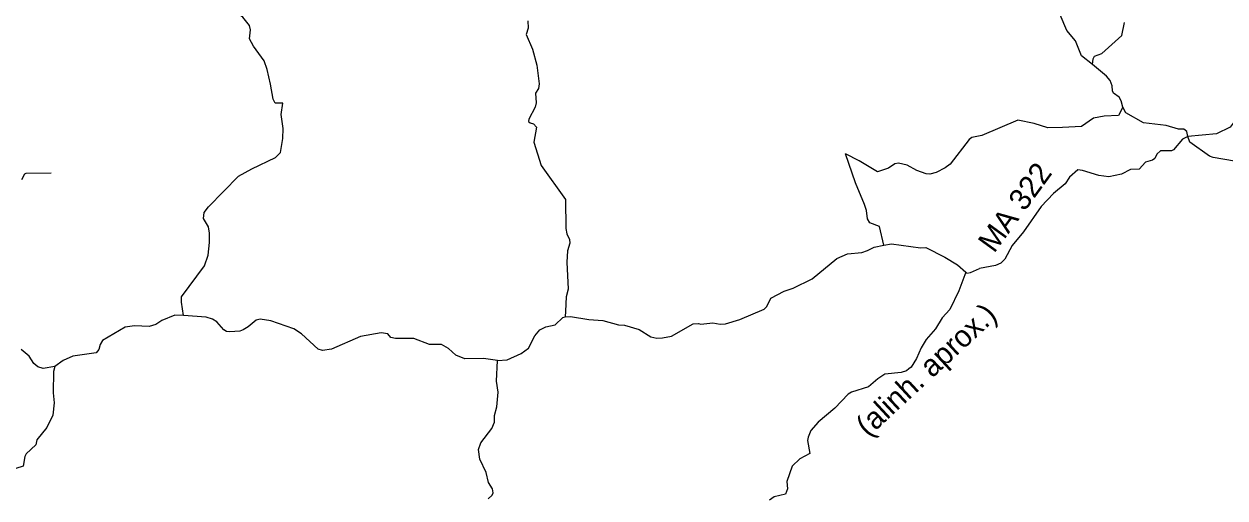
# Model space of a CAD drawing. Extents: x 332 to 501, y 9447 to 9559.
# Drawn here: x 427.75 to 448.76, y 9533.34 to 9541.64 of the extents above; entities that cross this region are included whole.
import ezdxf

# ---------------------------------------------------------------- set-up
doc = ezdxf.new("R2010")
doc.units = 0
for name, color, linetype in [('Level 31', 7, 'Continuous'), ('Level 5', 7, 'Continuous'), ('Level 6', 7, 'Continuous'), ('Level 7', 7, 'Continuous')]:
    doc.layers.add(name, color=color, linetype=linetype)

msp = doc.modelspace()

# ---------------------------------------------------------------- linework, layer by layer
at = {"layer": 'Level 5'}
for points in [[(432.2736, 9540.2543), (432.1396, 9540.2564), (432.1044, 9540.3252), (432.0629, 9540.5874), (432.0037, 9540.8432), (431.9493, 9540.9983), (431.7606, 9541.2542), (431.6919, 9541.3805), (431.7079, 9541.5404), (431.6935, 9541.6123), (431.5768, 9541.7626), (431.4281, 9541.857), (431.3849, 9541.9241), (431.3769, 9542.0329), (431.447, 9542.1738), (431.4412, 9542.3762), (431.5784, 9542.7652), (431.5944, 9542.8675), (431.4952, 9543.1745), (431.468, 9543.5839), (431.4041, 9543.7374), (431.2237, 9544.0586), (431.156, 9544.2217)], [(446.4423, 9540.9311), (446.2536, 9541.082), (446.1463, 9541.3459), (445.9948, 9541.5276), (445.88, 9541.8002)], [(446.4423, 9540.9311), (446.4579, 9541.0297), (446.4814, 9541.075), (446.6045, 9541.1224), (446.9578, 9541.4405), (447.0045, 9541.6664)], [(446.9746, 9540.1859), (446.9478, 9540.297), (446.9102, 9540.3612), (446.8127, 9540.432), (446.7939, 9540.4695), (446.7892, 9540.5571), (446.7509, 9540.6517), (446.6903, 9540.7249), (446.4423, 9540.9311)], [(430.5402, 9536.5403), (430.5036, 9536.7733), (430.5055, 9536.8634), (430.9036, 9537.4086), (430.9713, 9537.5924), (430.9947, 9537.818), (430.9915, 9537.9811), (430.9772, 9538.0898), (430.886, 9538.2353), (430.9022, 9538.3429), (430.974, 9538.4416), (431.5032, 9538.9772), (431.7367, 9539.1083), (432.1474, 9539.3034), (432.2352, 9539.392), (432.2771, 9539.6344), (432.2832, 9539.8105), (432.2472, 9540.0564), (432.2736, 9540.2543)], [(446.9746, 9540.1859), (446.8976, 9540.0372), (446.6488, 9540.0286), (446.46, 9539.9943), (446.254, 9539.8484), (445.9194, 9539.8313), (445.662, 9539.8227), (445.4217, 9539.8999), (445.1385, 9539.96), (444.5075, 9539.6862)], [(448.0425, 9539.8014), (447.9458, 9539.7996), (447.7353, 9539.8616), (447.3388, 9539.9106), (447.0244, 9540.0843), (446.9746, 9540.1859)], [(449.4204, 9540.23), (449.1918, 9540.2541), (449.0278, 9540.2528), (448.9486, 9540.1812), (448.922, 9539.9309), (448.8547, 9539.837), (448.6138, 9539.7165), (448.1107, 9539.6687)], [(448.1107, 9539.6687), (448.0163, 9539.6243), (447.863, 9539.4397), (447.8255, 9539.4178), (447.6315, 9539.4194), (447.5705, 9539.3615), (447.5372, 9539.2886), (447.4955, 9539.257), (447.3719, 9539.2216), (447.262, 9539.1018), (447.1068, 9539.0967), (446.9541, 9539.0147), (446.7282, 9538.9655), (446.5565, 9538.9894), (446.2713, 9539.0778), (446.1892, 9539.0879), (446.0395, 9538.9613)], [(448.1107, 9539.6687), (448.0925, 9539.7592), (448.0425, 9539.8014)], [(448.5551, 9539.3031), (448.493, 9539.3273), (448.1489, 9539.5746), (448.1107, 9539.6687)], [(448.9279, 9539.2381), (448.5551, 9539.3031)], [(446.0395, 9538.9613), (445.9646, 9538.843), (445.7588, 9538.6751), (445.548, 9538.4442), (445.2338, 9538.0037), (445.0381, 9537.7652), (444.9081, 9537.5216), (444.84, 9537.4559), (444.7491, 9537.4118), (444.4645, 9537.3604)], [(437.6307, 9536.4709), (437.8735, 9536.4493), (438.1517, 9536.3741), (438.2541, 9536.3693), (438.5099, 9536.2958), (438.7178, 9536.1662), (438.8201, 9536.1439), (438.9224, 9536.147), (439.0759, 9536.179), (439.4581, 9536.3933), (439.5524, 9536.3981), (439.5908, 9536.3853), (439.7987, 9536.4077), (439.9314, 9536.3869), (440.0202, 9536.3923), (440.275, 9536.4709), (440.7007, 9536.6519), (440.7449, 9536.6931), (440.814, 9536.8394), (441.0507, 9536.9657), (441.2058, 9537.0153), (441.5361, 9537.1774), (441.9701, 9537.5372), (442.1571, 9537.6164), (442.4064, 9537.644), (442.5047, 9537.674), (442.6222, 9537.7363), (442.7954, 9537.7712)], [(442.7954, 9537.7712), (442.9267, 9537.7903), (443.4315, 9537.7252), (443.5259, 9537.7284), (443.8604, 9537.5593), (444.0834, 9537.4238), (444.2303, 9537.296)], [(444.3068, 9537.2933), (444.4645, 9537.3604)], [(444.2303, 9537.296), (444.1049, 9536.9673), (443.9448, 9536.6459), (443.8121, 9536.4956), (443.6954, 9536.3022), (443.5307, 9536.1183), (443.4443, 9535.9744), (443.366, 9535.7873), (443.2731, 9535.635), (443.2291, 9535.602)], [(444.2303, 9537.296), (444.2456, 9537.2813), (444.3068, 9537.2933)], [(430.5402, 9536.5403), (430.388, 9536.5459), (430.1615, 9536.4516), (430.056, 9536.3803), (429.9394, 9536.3437), (429.6804, 9536.3597), (429.5173, 9536.3325), (429.1224, 9536.1007), (429.082, 9536.033), (429.0579, 9535.945), (429.0088, 9535.8848), (428.6027, 9535.8257), (428.4299, 9535.7489), (428.2847, 9535.646)], [(433.9992, 9536.234), (433.6363, 9536.1694), (433.1288, 9535.9511), (432.9679, 9535.928), (432.8944, 9535.9465), (432.6033, 9536.2174), (432.469, 9536.3069), (432.0693, 9536.4429), (431.8779, 9536.4724), (431.8118, 9536.4572), (431.6727, 9536.3373), (431.58, 9536.2846), (431.5224, 9536.2622), (431.3497, 9536.251), (431.2922, 9536.259), (431.2442, 9536.2862), (431.1211, 9536.4269), (431.0459, 9536.4716), (430.9372, 9536.5068), (430.5402, 9536.5403)], [(436.0331, 9535.7503), (436.2031, 9535.762), (436.4456, 9535.872), (436.5736, 9535.9648), (436.6839, 9536.1822), (436.7718, 9536.2862), (436.879, 9536.3389), (437.0421, 9536.3773), (437.1763, 9536.502), (437.2184, 9536.5173)], [(437.2184, 9536.5173), (437.3075, 9536.5212), (437.6307, 9536.4709)], [(436.0331, 9535.7503), (435.7885, 9535.7857), (435.4623, 9535.7793), (435.304, 9535.8448), (435.1761, 9535.9616), (435.0539, 9536.0299), (434.8419, 9536.0319), (434.5669, 9536.1343), (434.2496, 9536.1374), (434.1671, 9536.1534), (434.113, 9536.2169), (433.9992, 9536.234)], [(435.8684, 9533.3265), (435.9372, 9533.392), (435.9543, 9533.4367), (435.9475, 9533.5026), (435.8763, 9533.6142), (435.8316, 9533.7918), (435.7229, 9534.022), (435.7005, 9534.1947), (435.7421, 9534.3098), (435.934, 9534.5577), (435.9796, 9534.6702), (435.9819, 9534.7895), (436.0229, 9534.9388), (436.0459, 9535.1957), (436.0155, 9535.3916), (436.0331, 9535.7503)], [(428.2847, 9535.646), (428.262, 9535.557), (428.2553, 9535.1826), (428.2748, 9535.0102), (428.254, 9534.7927), (428.1485, 9534.5753), (427.9726, 9534.361), (427.9534, 9534.2731), (427.7871, 9534.1196), (427.7615, 9534.0716), (427.7343, 9533.9005), (427.4929, 9533.8237), (427.349, 9533.8062), (427.2531, 9533.8078), (427.0212, 9533.8669), (426.8693, 9533.8813), (426.7062, 9533.8221), (426.6519, 9533.8221), (426.6167, 9533.8317), (426.4008, 9533.9756), (426.2937, 9533.9756), (426.1306, 9533.9405)], [(443.2291, 9535.602), (443.1868, 9535.5703), (443.0981, 9535.5415), (442.8111, 9535.5107), (442.6858, 9535.4311), (442.5265, 9535.29), (442.2259, 9535.1973), (442.1684, 9535.1589), (441.9349, 9534.9142), (441.6423, 9534.6728), (441.5128, 9534.5241), (441.4664, 9534.409), (441.4584, 9534.3514), (441.4972, 9534.1199), (441.324, 9534.03), (441.1866, 9533.9021), (441.0937, 9533.6353), (441.105, 9533.504), (441.0729, 9533.411), (440.8715, 9533.3618), (440.7932, 9533.3049)]]:
    msp.add_lwpolyline(points, dxfattribs=at)
at = {"layer": 'Level 6'}
for points in [[(436.5624, 9541.6987), (436.5688, 9541.5692), (436.5368, 9541.4588), (436.6423, 9541.1982), (436.7207, 9540.92), (436.7622, 9540.5938), (436.7478, 9540.509), (436.6999, 9540.4323), (436.7063, 9540.2612), (436.6903, 9540.1829), (436.5821, 9539.9778), (436.5778, 9539.9351), (436.6045, 9539.9095), (436.6599, 9539.8934), (436.7127, 9539.8343), (436.6711, 9539.5721), (436.7942, 9539.1611), (437.2227, 9538.5679), (437.2275, 9538.061), (437.2467, 9537.9667), (437.2931, 9537.8691), (437.2995, 9537.8052), (437.2595, 9537.6693), (437.2435, 9537.4694), (437.2685, 9536.9968), (437.2339, 9536.865), (437.2213, 9536.6116)], [(442.7954, 9537.7712), (442.7168, 9538.0962), (442.5505, 9538.1586), (442.5057, 9538.2305), (442.4897, 9538.3776), (442.4562, 9538.48), (442.2995, 9538.8605), (442.1201, 9539.3659)], [(437.2213, 9536.6116), (437.2184, 9536.5173)]]:
    msp.add_lwpolyline(points, dxfattribs=at)
at = {"layer": 'Level 7'}
for points in [[(444.5075, 9539.6862), (444.3334, 9539.6536), (444.2838, 9539.6184), (443.9512, 9539.1883), (443.8648, 9539.1243), (443.7066, 9539.0412), (443.5978, 9539.014), (443.5339, 9539.0172), (443.3724, 9539.0764), (443.1981, 9539.1707), (443.051, 9539.2043), (442.987, 9539.1915), (442.8719, 9539.1195), (442.6816, 9539.054), (442.3586, 9539.2459), (442.1201, 9539.3659)], [(427.7072, 9538.9213), (427.7615, 9539.0188), (427.7849, 9539.0324), (428.2204, 9539.0332)], [(428.2847, 9535.646), (428.0829, 9535.613), (427.9902, 9535.637), (427.9209, 9535.697), (427.8367, 9535.8273), (427.6992, 9535.9424)]]:
    msp.add_lwpolyline(points, dxfattribs=at)

# ---------------------------------------------------------------- texts
at = {"layer": 'Level 31'}
for s, rotation, p in [('MA 322', 53.97263, (444.7223, 9537.6158)), ('(alinh. aprox.)', 42.80741, (442.5191, 9534.3975))]:
    msp.add_text(s, height=0.38, rotation=rotation, dxfattribs=at).set_placement(p)

doc.saveas('drawing.dxf')
